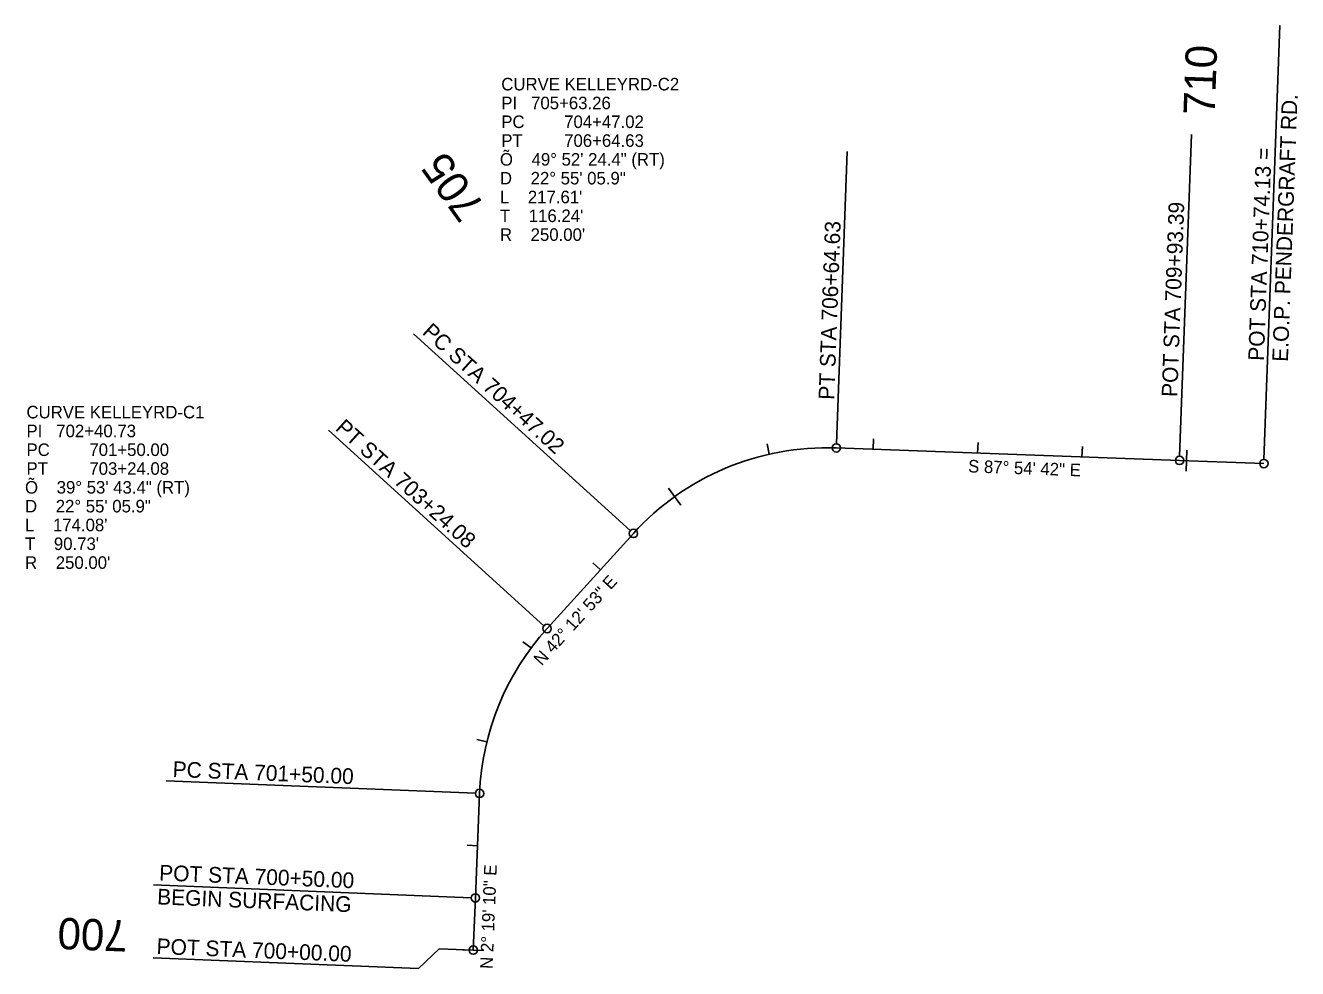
# Model space of a CAD drawing. Extents: x 2819977 to 2827606, y 116785 to 150320.
# Drawn here: x 2825066 to 2826284, y 129358 to 130260 of the extents above; entities that cross this region are included whole.
import ezdxf

# ---------------------------------------------------------------- set-up
doc = ezdxf.new("R2010")
doc.units = 0
for name, color, linetype in [('Roadway-Centerline main', 7, 'Continuous'), ('Roadway-Curve pc pt', 7, 'Continuous'), ('Text-Alignment info', 7, 'Continuous'), ('Text-Curve info', 7, 'Continuous')]:
    doc.layers.add(name, color=color, linetype=linetype)

msp = doc.modelspace()

# ---------------------------------------------------------------- linework, layer by layer
at = {"layer": 'Roadway-Centerline main'}
for p, q in [((2825877.6, 129854.7), (2825877.9, 129864.7)), ((2825778.1, 129850), (2825775.9, 129859.7)), ((2825842.2, 129856), (2826170.8, 129844)), ((2825977.5, 129851), (2825977.9, 129861)), ((2826077.4, 129847.4), (2826077.8, 129857.4)), ((2826177.4, 129843.7), (2826177.7, 129853.7)), ((2826170.8, 129844), (2826251.5, 129841)), ((2826177.4, 129843.7), (2826177, 129833.7)), ((2825687.4, 129809.3), (2825681.6, 129817.4)), ((2825687.4, 129809.3), (2825693.3, 129801.2)), ((2825565.4, 129683.1), (2825648, 129774.1)), ((2825616.4, 129739.3), (2825609, 129746)), ((2825550.1, 129664.5), (2825542, 129670.4)), ((2825507.7, 129574.6), (2825498, 129577)), ((2825496.7, 129425.3), (2825500.7, 129525.2)), ((2825498.7, 129475.2), (2825488.7, 129475.6)), ((2825494.7, 129375.3), (2825496.7, 129425.3)), ((2825494.7, 129375.3), (2825484.7, 129375.7)), ((2825494.7, 129375.3), (2825504.6, 129374.9))]:
    msp.add_line(p, q, dxfattribs=at)
for centre, start, end in [((2825833.1, 129606.1), 87.9117, 137.7851), ((2825750.5, 129515.1), 137.7851, 177.6805)]:
    msp.add_arc(centre, 250, start, end, dxfattribs=at)
at = {"layer": 'Roadway-Curve pc pt'}
for p, q in [((2826251.6, 129845), (2826266.7, 130260.3)), ((2826170.9, 129848), (2826182.1, 130155.8)), ((2825842.4, 129860), (2825852.6, 130139.5)), ((2825645, 129776.8), (2825437.5, 129965)), ((2825562.4, 129685.7), (2825356, 129873)), ((2825496.7, 129525.4), (2825200.8, 129537.3)), ((2825492.7, 129425.4), (2825188.5, 129437.8))]:
    msp.add_line(p, q, dxfattribs=at)
msp.add_lwpolyline([(2825188.3, 129367.9), (2825442.2, 129357.6), (2825462.1, 129376.6), (2825494.7, 129375.3)], dxfattribs=at)
for centre in [(2825842.2, 129856), (2826170.8, 129844), (2826251.5, 129841), (2825648, 129774.1), (2825565.4, 129683.1), (2825500.7, 129525.2), (2825496.7, 129425.3), (2825494.7, 129375.3)]:
    msp.add_circle(centre, 4, dxfattribs=at)

# ---------------------------------------------------------------- texts
at = {"layer": 'Roadway-Centerline main'}
for s, rotation, p in [(' 710', 87.9117, (2826204, 130163)), (' 705', 125.6426, (2825513.2, 130078.1)), (' 700', 177.6805, (2825175.5, 129403.3))]:
    msp.add_text(s, height=30, rotation=rotation, dxfattribs=at).set_placement(p)
at = {"layer": 'Roadway-Curve pc pt'}
for s, rotation, p in [('E.O.P. PENDERGRAFT RD.', 87.9117, (2826274.5, 129938.2)), ('POT STA 710+74.13 =', 87.9117, (2826251.5, 129939.1)), ('POT STA 709+93.39', 87.9117, (2826168.6, 129904.5)), ('PT STA 706+64.63', 87.9117, (2825840.2, 129901.8)), ('PC STA 704+47.02', 317.7851, (2825445, 129965.6)), ('PT STA 703+24.08', 317.7851, (2825361.8, 129873.7)), ('PC STA 701+50.00', 357.6805, (2825206.7, 129541.1)), ('POT STA 700+50.00', 357.6805, (2825193.8, 129442)), ('BEGIN SURFACING', 357.6805, (2825191.9, 129419.1)), ('POT STA 700+00.00', 357.6805, (2825191.3, 129371.6))]:
    msp.add_text(s, height=15, rotation=rotation, dxfattribs=at).set_placement(p)
at = {"layer": 'Text-Alignment info'}
for s, rotation, p in [('S 87%%d 54\' 42" E', 357.9117, (2825968.2, 129832.6)), ('N 42%%d 12\' 53" E', 47.7851, (2825560.2, 129646.8)), ('N 2%%d 19\' 10" E', 87.6805, (2825513.2, 129357.1))]:
    msp.add_text(s, height=12, rotation=rotation, dxfattribs=at).set_placement(p)
at = {"layer": 'Text-Curve info'}
for s, p in [('CURVE KELLEYRD-C2', (2825521.5, 130198.1)), ('PI   705+63.26', (2825521.5, 130180.1)), ('PC', (2825521.5, 130162.1)), ('704+47.02', (2825581.7, 130162.1)), ('PT', (2825521.5, 130144.1)), ('706+64.63', (2825581.7, 130144.1)), ('Õ    49%%d 52\' 24.4" (RT)', (2825520.2, 130126.1)), ('D    22%%d 55\' 05.9"', (2825520.2, 130108.1)), ("L    217.61'", (2825520.2, 130090.1)), ("T    116.24'", (2825520.2, 130072.1)), ("R    250.00'", (2825520.2, 130054.1)), ('CURVE KELLEYRD-C1', (2825067, 129884.2)), ('PI   702+40.73', (2825067, 129866.2)), ('PC', (2825067, 129848.2)), ('701+50.00', (2825127.2, 129848.2)), ('PT', (2825067, 129830.2)), ('703+24.08', (2825127.2, 129830.2)), ('Õ    39%%d 53\' 43.4" (RT)', (2825065.6, 129812.2)), ('D    22%%d 55\' 05.9"', (2825065.6, 129794.2)), ("L    174.08'", (2825065.6, 129776.2)), ("T    90.73'", (2825065.6, 129758.2)), ("R    250.00'", (2825065.6, 129740.2))]:
    msp.add_text(s, height=12, dxfattribs=at).set_placement(p)

doc.saveas('drawing.dxf')
